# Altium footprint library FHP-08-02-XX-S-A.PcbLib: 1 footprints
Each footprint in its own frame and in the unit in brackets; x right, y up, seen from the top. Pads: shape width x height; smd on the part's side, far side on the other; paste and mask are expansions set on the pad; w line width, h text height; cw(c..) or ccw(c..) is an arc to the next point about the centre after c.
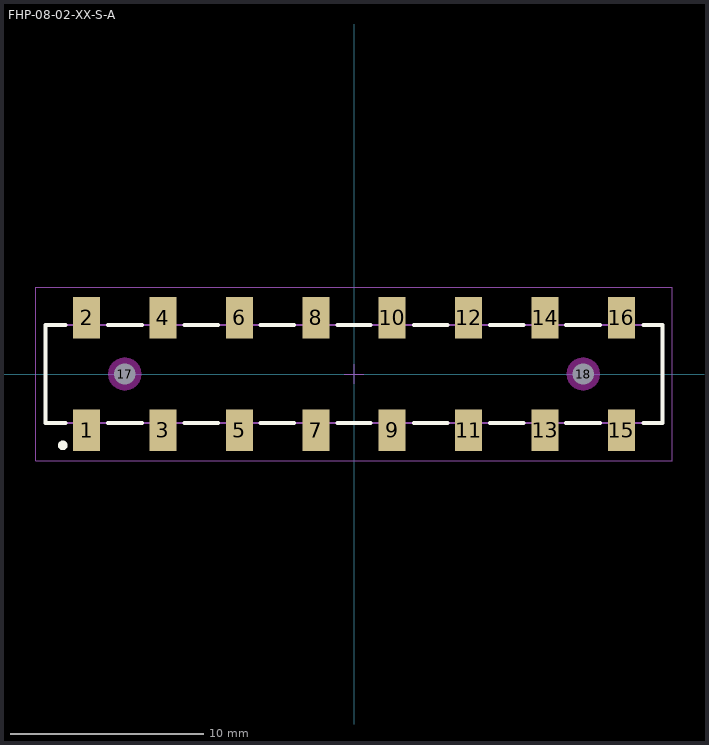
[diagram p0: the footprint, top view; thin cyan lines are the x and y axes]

## FHP-08-02-XX-S-A [mm] "3.96mm pitch, 8 pin, power socket strip; w/alignment pins"
height 9.35
pads (18):
  rect 1.4x2.15 smd mask+0: 1(-13.868,-2.921) 2(-13.868,2.921) 3(-9.906,-2.921) 4(-9.906,2.921) 5(-5.944,-2.921) 6(-5.944,2.921) 7(-1.981,-2.921) 8(-1.981,2.921) 9(1.981,-2.921) 10(1.981,2.921) 11(5.944,-2.921) 12(5.944,2.921) 13(9.906,-2.921) 14(9.906,2.921) 15(13.868,-2.921) 16(13.868,2.921)
  round 1 hole 1.1 unplated mask+0: 17(-11.887,0) 18(11.887,0)
Top Overlay:
  circle w0.25: c-15.1,-3.7 r0.125
  lines w0.2: -14.95,-2.55 -16,-2.55 -16,2.55 -14.95,2.55 ; -12.75,-2.55 -11,-2.55 ; -12.75,2.55 -11,2.55 ; -8.8,-2.55 -7.05,-2.55 ; -8.8,2.55 -7.05,2.55 ; -4.85,-2.55 -3.1,-2.55 ; -4.85,2.55 -3.1,2.55 ; -0.85,-2.55 0.85,-2.55 ; -0.85,2.55 0.85,2.55 ; 3.1,-2.55 4.85,-2.55 ; 3.1,2.55 4.85,2.55 ; 7.05,-2.55 8.8,-2.55 ; 7.05,2.55 8.8,2.55 ; 11,-2.55 12.75,-2.55 ; 11,2.55 12.75,2.55 ; 15,-2.55 16,-2.55 16,2.55 15,2.55
Keep-Out Layer:
  pour cut-out: 12.744,0 12.715,0.222 12.629,0.429 12.493,0.606 12.316,0.742 12.109,0.828 11.887,0.857 11.665,0.828 11.458,0.742 11.281,0.606 11.145,0.429 11.059,0.222 11.03,0 11.059,-0.222 11.145,-0.429 11.281,-0.606 11.458,-0.742 11.665,-0.828 11.887,-0.857 12.109,-0.828 12.316,-0.742 12.493,-0.606 12.629,-0.429 12.715,-0.222
  pour cut-out: -11.03,0 -11.059,0.222 -11.145,0.429 -11.281,0.606 -11.458,0.742 -11.665,0.828 -11.887,0.857 -12.109,0.828 -12.316,0.742 -12.493,0.606 -12.629,0.429 -12.715,0.222 -12.744,0 -12.715,-0.222 -12.629,-0.429 -12.493,-0.606 -12.316,-0.742 -12.109,-0.828 -11.887,-0.857 -11.665,-0.828 -11.458,-0.742 -11.281,-0.606 -11.145,-0.429 -11.059,-0.222
Mechanical 12:
  lines w0.001: -16,-2.55 -16,2.55 16,2.55 16,-2.55 -16,-2.55
Mechanical 13:
  lines w0.1: -16,-2.55 -16,2.55 16,2.55 16,-2.55 -16,-2.55
  text ".Designator" at 0,0 h1.52
Mechanical 15:
  lines w0.05: -0.5,0 0.5,0 ; 0,-0.5 0,0.5 ; -16.5,-4.5 -16.5,4.5 16.5,4.5 16.5,-4.5 -16.5,-4.5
